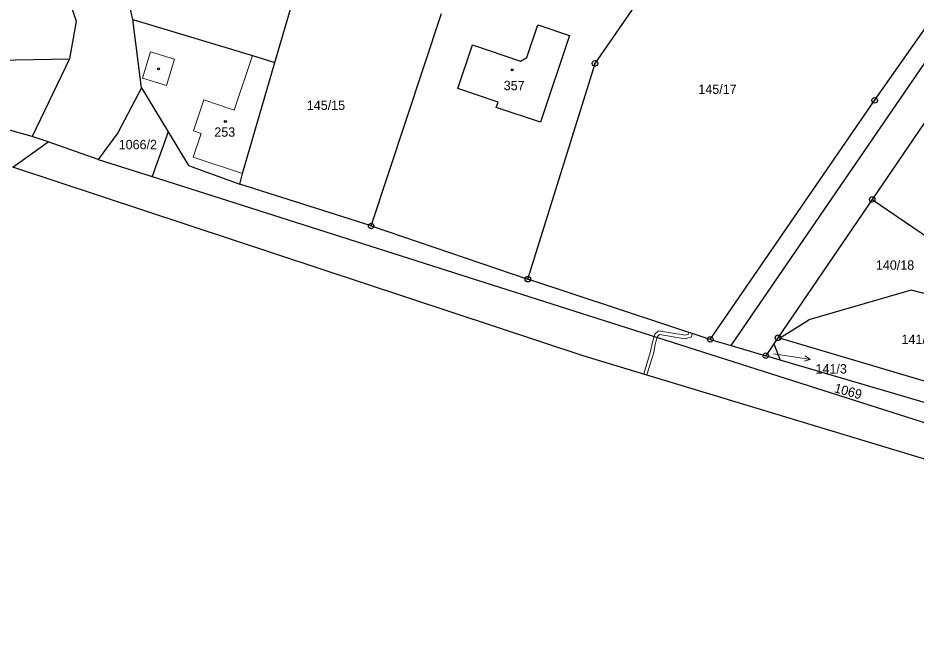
# Model space of a CAD drawing. Extents: x -694609 to -690140, y -1033292 to -1029794.
# Drawn here: x -692949.2 to -692786, y -1031838.9 to -1031724.9 of the extents above; entities that cross this region are included whole.
import ezdxf
from ezdxf.enums import TextEntityAlignment as Align

# ---------------------------------------------------------------- set-up
doc = ezdxf.new("R2010")
doc.units = 0
doc.header["$LTSCALE"] = 0.68
for name, color, linetype, lineweight in [('1', 7, 'Continuous', 25), ('13', 7, 'Continuous', 13), ('4', 7, 'Continuous', 13), ('5', 7, 'Continuous', 25), ('7', 7, 'Continuous', 13), ('8', 7, 'Continuous', 25)]:
    doc.layers.add(name, color=color, linetype=linetype, lineweight=lineweight)
doc.layers.add('2', color=7, linetype='Continuous')

msp = doc.modelspace()

# ---------------------------------------------------------------- linework, layer by layer
at = {"layer": '1'}
for p, q in [((-692819.56, -1031784.34), (-692707.53, -1031620.78)), ((-692844.31, -1031733.12), (-692813.53, -1031688.62)), ((-692944.11, -1031708.76), (-692938.58, -1031725.46)), ((-692928.25, -1031725.18), (-692930.98, -1031713.14)), ((-692793.51, -1031739.84), (-692775.19, -1031713.68)), ((-692902.47, -1031732.95), (-692897.59, -1031716.17)), ((-692926.69, -1031737.58), (-692928.25, -1031725.18)), ((-692928.25, -1031725.18), (-692906.54, -1031731.68)), ((-692884.99, -1031762.64), (-692872.2, -1031724.07)), ((-692938.58, -1031725.46), (-692939.76, -1031732.28)), ((-692856.7, -1031732.06), (-692854.69, -1031726.12)), ((-692854.69, -1031726.12), (-692848.95, -1031728.05)), ((-692946.57, -1031746.38), (-693007.59, -1031729.72)), ((-692869.25, -1031737.68), (-692866.55, -1031729.75)), ((-692866.55, -1031729.75), (-692857.84, -1031732.72)), ((-692906.54, -1031731.68), (-692902.47, -1031732.95)), ((-692953.28, -1031732.56), (-692939.76, -1031732.28)), ((-692939.76, -1031732.28), (-692946.57, -1031746.38)), ((-692908.34, -1031753.13), (-692902.47, -1031732.95)), ((-692857.84, -1031732.72), (-692856.7, -1031732.06)), ((-692856.51, -1031772.3), (-692844.31, -1031733.12)), ((-692926.69, -1031737.58), (-692931.02, -1031745.72)), ((-692926.69, -1031737.58), (-692921.85, -1031745.57)), ((-692861.93, -1031740.18), (-692869.25, -1031737.68)), ((-692823.37, -1031783.22), (-692793.51, -1031739.84)), ((-692862.25, -1031741.13), (-692861.93, -1031740.18)), ((-692782.68, -1031741.3), (-692793.95, -1031757.82)), ((-692943.65, -1031747.39), (-692946.57, -1031746.38)), ((-692931.02, -1031745.72), (-692934.55, -1031750.54)), ((-692921.85, -1031745.57), (-692924.78, -1031753.65)), ((-692921.85, -1031745.57), (-692918.15, -1031751.67)), ((-692950.08, -1031751.98), (-692943.65, -1031747.39)), ((-692934.55, -1031750.54), (-692943.65, -1031747.39)), ((-692934.55, -1031750.54), (-692924.78, -1031753.65)), ((-692846.26, -1031786.25), (-692950.08, -1031751.98)), ((-692918.15, -1031751.67), (-692908.81, -1031755.05)), ((-692924.78, -1031753.65), (-692657.06, -1031838.9)), ((-692908.81, -1031755.05), (-692908.34, -1031753.13)), ((-692884.99, -1031762.64), (-692908.81, -1031755.05)), ((-692793.95, -1031757.82), (-692811.08, -1031782.94)), ((-692793.95, -1031757.82), (-692743.63, -1031792.14)), ((-692884.99, -1031762.64), (-692856.51, -1031772.3)), ((-692823.37, -1031783.22), (-692856.51, -1031772.3)), ((-692786.89, -1031774.27), (-692805.46, -1031779.68)), ((-692776.66, -1031777.04), (-692786.89, -1031774.27)), ((-692810.78, -1031783.03), (-692805.46, -1031779.68)), ((-692823.37, -1031783.22), (-692819.56, -1031784.34)), ((-692811.85, -1031784.06), (-692813.29, -1031786.19)), ((-692811.08, -1031782.94), (-692811.85, -1031784.06)), ((-692811.85, -1031784.06), (-692810.69, -1031787)), ((-692810.78, -1031783.03), (-692811.08, -1031782.94)), ((-692765.5, -1031796.39), (-692810.78, -1031783.03)), ((-692819.56, -1031784.34), (-692813.29, -1031786.19)), ((-692716.71, -1031825.45), (-692846.26, -1031786.25)), ((-692810.69, -1031787), (-692813.29, -1031786.19)), ((-692765.82, -1031800.2), (-692810.69, -1031787))]:
    msp.add_line(p, q, dxfattribs=at)
msp.add_lwpolyline([(-692848.95, -1031728.05), (-692854.24, -1031743.81), (-692862.25, -1031741.13)], dxfattribs=at)
at = {"layer": '13'}
for points in [[(-692833, -1031782.88), (-692832.92, -1031782.62), (-692832.61, -1031782.34), (-692827.92, -1031783.11), (-692826.8, -1031782.76), (-692826.67, -1031782.13), (-692827.25, -1031781.94), (-692827.32, -1031782.3), (-692827.96, -1031782.49), (-692832.8, -1031781.7), (-692833.44, -1031782.28), (-692833.57, -1031782.69)], [(-692835.47, -1031789.51), (-692834.9, -1031789.69), (-692833.65, -1031785.59), (-692833.37, -1031784.11), (-692833, -1031782.88), (-692833.57, -1031782.69), (-692833.95, -1031783.97), (-692834.23, -1031785.45)]]:
    msp.add_lwpolyline(points, close=True, dxfattribs=at)
at = {"layer": '4'}
for p, q in [((-692920.73, -1031732.36), (-692925.06, -1031731.04)), ((-692906.54, -1031731.68), (-692909.86, -1031741.59)), ((-692920.73, -1031732.36), (-692922.19, -1031737.14)), ((-692915.36, -1031739.75), (-692917.25, -1031745.39)), ((-692909.86, -1031741.59), (-692915.36, -1031739.75)), ((-692915.88, -1031745.85), (-692917.31, -1031750.12)), ((-692917.25, -1031745.39), (-692915.88, -1031745.85)), ((-692908.34, -1031753.13), (-692917.31, -1031750.12))]:
    msp.add_line(p, q, dxfattribs=at)
msp.add_lwpolyline([(-692925.06, -1031731.04), (-692926.52, -1031735.82), (-692922.19, -1031737.14)], dxfattribs=at)
at = {"layer": '5'}
for centre in [(-692923.6268, -1031734.1292), (-692859.3668, -1031734.2692), (-692911.4768, -1031743.6492)]:
    msp.add_circle(centre, 0.175, dxfattribs=at)
at = {"layer": '7'}
msp.add_line((-692805.246, -1031786.869), (-692806.157, -1031786.218), dxfattribs=at)
msp.add_lwpolyline([(-692811.86, -1031785.83), (-692808.21, -1031786.4), (-692805.246, -1031786.869), (-692806.313, -1031787.207)], dxfattribs=at)
at = {"layer": '8'}
for centre, radius in [((-692844.31, -1031733.1199), 0.5), ((-692844.31, -1031733.1199), 0.0303), ((-692793.51, -1031739.8399), 0.5), ((-692793.51, -1031739.8399), 0.0303), ((-692793.95, -1031757.8199), 0.5), ((-692793.95, -1031757.8199), 0.0303), ((-692884.99, -1031762.6399), 0.5), ((-692884.99, -1031762.6399), 0.0303), ((-692856.51, -1031772.2999), 0.5), ((-692856.51, -1031772.2999), 0.0303), ((-692811.08, -1031782.9399), 0.5), ((-692823.37, -1031783.2199), 0.5), ((-692823.37, -1031783.2199), 0.0303), ((-692811.08, -1031782.9399), 0.0303), ((-692813.29, -1031786.1899), 0.5), ((-692813.29, -1031786.1899), 0.0303)]:
    msp.add_circle(centre, radius, dxfattribs=at)

# ---------------------------------------------------------------- texts
at = {"layer": '2'}
for s, p in [('357', (-692858.999, -1031737.995)), ('145/17', (-692822.06, -1031738.655)), ('145/15', (-692893.19, -1031741.575)), ('253', (-692911.579, -1031746.435)), ('1066/2', (-692927.37, -1031748.705)), ('140/18', (-692789.8, -1031770.585)), ('141/1', (-692785.78, -1031784.065))]:
    msp.add_text(s, height=1.7, dxfattribs=at).set_placement(p, align=Align.CENTER)
msp.add_text('141/3', height=1.7, dxfattribs=at).set_placement((-692804.25, -1031789.425))
msp.add_text('1069', height=1.7, rotation=345, dxfattribs=at).set_placement((-692798.528, -1031793.4595), align=Align.CENTER)

doc.saveas('drawing.dxf')
